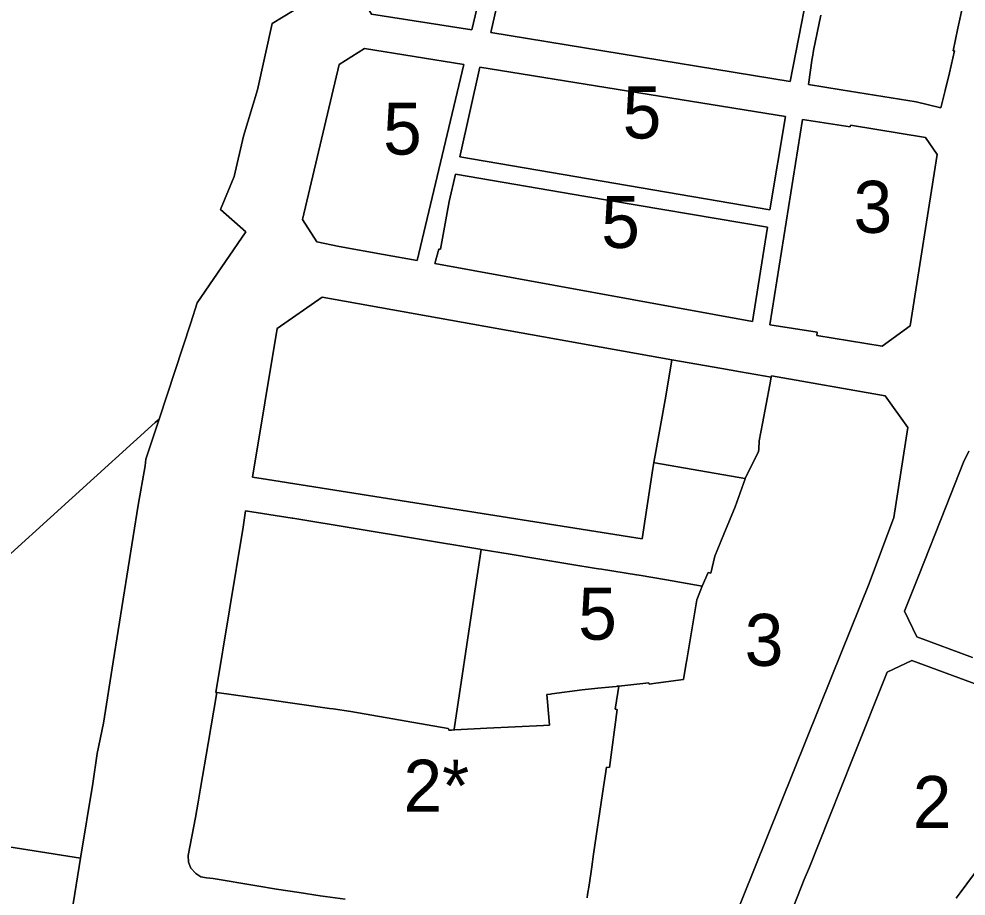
# Model space of a CAD drawing. Extents: x 598968 to 613553, y 4409678 to 4430833.
# Drawn here: x 607149.2 to 607367.7, y 4416375.4 to 4416577.8 of the extents above; entities that cross this region are included whole.
import ezdxf

# ---------------------------------------------------------------- set-up
doc = ezdxf.new("R2010")
doc.units = 0
for name, color, linetype in [('1', 7, 'Continuous'), ('Sòl Rústic Protegit', 7, 'Continuous'), ('ZONA 2. CARRERS DE CASES. Cases de trast', 7, 'Continuous'), ("ZONA 2_. CARRERS DE CASES. Afectades a ús d'aparcament", 7, 'Continuous'), ("ZONA 3. ILLES  D'EDIFICIS ENTRE MITGERES. EIXAMPLE.", 7, 'Continuous'), ('ZONA 5. CASES UNIFAMILIARS EN RENGLE', 7, 'Continuous')]:
    doc.layers.add(name, color=color, linetype=linetype)

msp = doc.modelspace()

# ---------------------------------------------------------------- linework, layer by layer
at = {"layer": '1'}
for points in [[(607253.6812, 4416575.2516), (607230.5315, 4416578.8312), (607227.1615, 4416584.5111), (607240.1011, 4416639.1907), (607245.621, 4416643.0107), (607268.9208, 4416639.2012)], [(607258.0512, 4416574.6517), (607264.851, 4416604.5115), (607302.0556, 4416598.43), (607333.0202, 4416593.3728), (607329.7503, 4416576.7029), (607327.1804, 4416563.333)], [(607241.0715, 4416522.002), (607233.2926, 4416523.3829), (607223.1303, 4416525.2361), (607217.9218, 4416526.2916), (607214.6264, 4416531.5106), (607223.0816, 4416567.2612), (607228.9215, 4416570.9112), (607251.8312, 4416567.2717)], [(607322.5005, 4416533.7433), (607250.9113, 4416545.9319), (607255.5612, 4416566.5918), (607326.1005, 4416555.2335)], [(607354.8802, 4416506.9342), (607348.3603, 4416502.2341), (607333.3105, 4416504.7138), (607333.4205, 4416505.4638), (607322.5006, 4416507.1636), (607330.0304, 4416554.5732), (607341.0102, 4416552.8834), (607341.0702, 4416553.2434), (607358.38, 4416550.4337), (607361.05, 4416546.4438)], [(607245.1615, 4416521.3521), (607246.0815, 4416524.6721), (607246.4815, 4416524.6321), (607248.4704, 4416535.6503), (607249.9414, 4416541.9019), (607280.021, 4416536.7625), (607321.9505, 4416529.7133), (607318.4807, 4416507.9235)], [(607299.8135, 4416499.0644), (607219.1718, 4416513.5817), (607208.792, 4416506.2916), (607203.0922, 4416472.0218), (607206.5921, 4416471.4919), (607293.0312, 4416457.7836), (607295.4811, 4416474.0434), (607295.7181, 4416475.3748), (607298.4534, 4416490.7421)], [(607322.7915, 4416495.1106), (607322.7639, 4416495.1107), (607315.7097, 4416496.3465), (607311.3629, 4416497.1079), (607299.8241, 4416499.1291), (607299.8135, 4416499.0644), (607298.4534, 4416490.7421), (607295.7181, 4416475.3748), (607295.9347, 4416475.3316), (607316.7188, 4416471.7323), (607316.7987, 4416471.7185), (607316.8655, 4416471.8538), (607319.8252, 4416477.9597), (607319.9193, 4416478.5087), (607320.0407, 4416480.4138), (607320.8007, 4416484.4437), (607322.4545, 4416493.3044)], [(607163.4465, 4416384.1234), (607166.2737, 4416401.3843), (607167.2644, 4416408.2936), (607168.6943, 4416415.2534), (607170.9668, 4416429.4365), (607176.7537, 4416465.5525), (607178.3436, 4416474.6524), (607178.5036, 4416476.1423), (607181.5374, 4416485.3831), (607180.6417, 4416484.6408), (607142.2689, 4416449.8628), (607128.5101, 4416464.9802), (607049.7261, 4416480.7842), (607041.8879, 4416473.8212), (607034.4301, 4416467.1962), (607020.2629, 4416454.6108), (607008.6601, 4416449.6102), (606998.8249, 4416429.3186), (606991.3041, 4416413.8024), (606990.5165, 4416412.1774), (607085.9131, 4416396.7506), (607115.4633, 4416391.7362), (607117.6201, 4416391.3702)], [(607255.8616, 4416455.3329), (607255.5325, 4416455.3874), (607212.3821, 4416462.5321), (607212.2621, 4416462.5521), (607201.5169, 4416464.241), (607200.9222, 4416460.5219), (607194.6724, 4416422.3422), (607194.8418, 4416422.3183), (607194.8424, 4416422.3222), (607205.8323, 4416420.8025), (607206.4601, 4416420.7127), (607220.864, 4416418.6531), (607221.6723, 4416418.5376), (607225.7621, 4416417.9528), (607248.2585, 4416414.0139), (607248.2618, 4416414.0133), (607248.2908, 4416413.9366), (607248.4018, 4416413.6433), (607249.0068, 4416413.6737), (607249.6118, 4416413.7041), (607249.6418, 4416413.9037), (607254.1827, 4416444.1494)]]:
    msp.add_lwpolyline(points, close=True, dxfattribs=at)
for points in [[(607212.6721, 4416579.7513), (607207.6022, 4416576.7012), (607204.2785, 4416561.4214), (607201.0126, 4416550.7016), (607198.9026, 4416541.3817), (607195.7021, 4416533.7618), (607201.5675, 4416528.6372), (607190.3531, 4416512.222), (607188.8352, 4416507.6121), (607181.5374, 4416485.3831), (607178.5036, 4416476.1423), (607178.3436, 4416474.6524), (607176.7537, 4416465.5525), (607170.9668, 4416429.4365), (607168.6943, 4416415.2534), (607167.2644, 4416408.2936), (607166.2737, 4416401.3843), (607163.4465, 4416384.1234), (607161.4063, 4416371.6676)], [(607366.9798, 4416580.8535), (607365.8299, 4416575.6036), (607364.7899, 4416570.4336), (607365.0599, 4416570.3836), (607363.9099, 4416565.3236), (607362.8965, 4416561.2696), (607361.9498, 4416557.2437), (607356.22, 4416558.6336), (607338.9002, 4416561.3633), (607331.4103, 4416562.6331), (607332.2003, 4416568.6831), (607332.2803, 4416568.9031), (607332.5403, 4416570.443), (607334.2002, 4416578.663)], [(607224.4559, 4416374.6879), (607218.7376, 4416375.4571), (607213.8916, 4416376.2053), (607208.6375, 4416377.004), (607204.084, 4416377.7469), (607194.0554, 4416379.3943), (607192.51, 4416379.6008), (607191.1526, 4416379.8327), (607190.0126, 4416380.5926), (607188.8726, 4416381.8326), (607188.2926, 4416383.2226), (607188.2391, 4416384.7221), (607189.9626, 4416393.4725), (607190.5526, 4416397.0225), (607191.1125, 4416400.2424), (607192.8725, 4416410.5923), (607194.8418, 4416422.3183), (607194.6724, 4416422.3422), (607200.9222, 4416460.5219), (607201.5169, 4416464.241), (607212.2621, 4416462.5521), (607212.3821, 4416462.5321), (607255.5325, 4416455.3874), (607255.8616, 4416455.3329), (607255.8665, 4416455.3357), (607262.5552, 4416454.2279), (607268.4785, 4416453.2604), (607276.7563, 4416451.8876), (607282.3888, 4416450.9775), (607282.913, 4416450.897), (607283.6455, 4416450.7844), (607291.6767, 4416449.5076), (607292.3377, 4416449.3946), (607298.5834, 4416448.3268), (607306.8637, 4416446.8654), (607306.8772, 4416446.8978), (607308.211, 4416450.0639), (607308.861, 4416449.8839), (607309.7609, 4416453.8039), (607311.8709, 4416458.8639), (607313.1559, 4416462.0139), (607314.4409, 4416465.1638), (607316.7508, 4416471.6238), (607316.7987, 4416471.7185), (607316.7188, 4416471.7323), (607295.9347, 4416475.3316), (607295.7181, 4416475.3748), (607295.4811, 4416474.0434), (607293.0312, 4416457.7836), (607206.5921, 4416471.4919), (607203.0922, 4416472.0218), (607208.792, 4416506.2916), (607219.1718, 4416513.5817), (607299.8135, 4416499.0644), (607299.8241, 4416499.1291), (607311.3629, 4416497.1079), (607315.7097, 4416496.3465), (607322.7639, 4416495.1107), (607322.7915, 4416495.1106), (607322.8406, 4416495.3736), (607349.0704, 4416490.7641), (607354.3303, 4416483.4643), (607351.0404, 4416462.6845), (607345.3706, 4416447.5046), (607336.7307, 4416426.0747), (607313.1112, 4416367.1749)], [(607369.2138, 4416430.4319), (607356.3705, 4416435.2149), (607353.5672, 4416441.0944), (607356.7654, 4416449.1648), (607363.1304, 4416465.315), (607363.1446, 4416465.3509), (607367.1502, 4416475.5146), (607368.3879, 4416478.0158)], [(607368.3879, 4416478.0158), (607367.1502, 4416475.5146), (607363.1446, 4416465.3509), (607363.1304, 4416465.315), (607356.7654, 4416449.1648), (607353.5672, 4416441.0944), (607356.3705, 4416435.2149), (607369.2138, 4416430.4319)], [(607325.5011, 4416366.6452), (607330.411, 4416379.1751), (607331.631, 4416382.0451), (607336.2109, 4416393.685), (607341.62, 4416407.2132), (607349.5406, 4416427.0349), (607355.2105, 4416429.725), (607385.6902, 4416418.5156), (607382.1903, 4416409.3257), (607379.5603, 4416411.3356), (607374.7104, 4416405.2856), (607374.9704, 4416405.1856), (607373.2804, 4416403.1556), (607381.3603, 4416396.6858), (607377.5854, 4416391.5608), (607377.7055, 4416391.711), (607379.9804, 4416389.5359), (607387.2703, 4416382.4361), (607385.9204, 4416372.4362)]]:
    msp.add_lwpolyline(points, dxfattribs=at)
at = {"layer": 'Sòl Rústic Protegit'}
for points in [[(607142.2689, 4416449.8628), (607180.6417, 4416484.6408), (607181.5374, 4416485.3831), (607188.8352, 4416507.6121), (607190.3531, 4416512.222), (607201.5675, 4416528.6372), (607195.7021, 4416533.7618), (607198.9026, 4416541.3817), (607201.0126, 4416550.7016), (607204.2785, 4416561.4214), (607207.6022, 4416576.7012), (607212.6721, 4416579.7513)], [(607161.4063, 4416371.6676), (607163.4465, 4416384.1234), (607117.6201, 4416391.3702)]]:
    msp.add_lwpolyline(points, dxfattribs=at)
at = {"layer": 'ZONA 2. CARRERS DE CASES. Cases de trast'}
for points in [[(607334.2002, 4416578.663), (607332.5403, 4416570.443), (607332.2803, 4416568.9031), (607332.2003, 4416568.6831), (607331.4103, 4416562.6331), (607338.9002, 4416561.3633), (607356.22, 4416558.6336), (607361.9498, 4416557.2437), (607362.8965, 4416561.2696), (607363.9099, 4416565.3236), (607365.0599, 4416570.3836), (607364.7899, 4416570.4336), (607365.8299, 4416575.6036), (607366.9798, 4416580.8535)], [(607365.4306, 4416374.8958), (607366.3606, 4416376.1358), (607374.0904, 4416386.4658), (607375.4404, 4416388.2658), (607375.4549, 4416388.2879), (607377.322, 4416391.1277), (607377.7055, 4416391.711), (607377.5854, 4416391.5608), (607381.3603, 4416396.6858), (607373.2804, 4416403.1556), (607374.9704, 4416405.1856), (607374.7104, 4416405.2856), (607379.5603, 4416411.3356), (607382.1903, 4416409.3257), (607385.6902, 4416418.5156), (607355.2105, 4416429.725), (607349.5406, 4416427.0349), (607341.62, 4416407.2132), (607336.2109, 4416393.685), (607331.631, 4416382.0451), (607330.411, 4416379.1751), (607325.5011, 4416366.6452)], [(607385.9204, 4416372.4362), (607387.2703, 4416382.4361), (607379.9804, 4416389.5359), (607377.7055, 4416391.711), (607377.322, 4416391.1277), (607375.4549, 4416388.2879), (607375.4404, 4416388.2658), (607374.0904, 4416386.4658), (607366.3606, 4416376.1358), (607365.4306, 4416374.8958)]]:
    msp.add_lwpolyline(points, dxfattribs=at)
at = {"layer": "ZONA 2_. CARRERS DE CASES. Afectades a ús d'aparcament"}
msp.add_lwpolyline([(607280.3177, 4416374.9462), (607280.4172, 4416375.7313), (607280.7477, 4416377.8843), (607281.3762, 4416382.1063), (607281.7893, 4416385.0136), (607283.8515, 4416399.0041), (607284.7515, 4416405.134), (607285.5014, 4416405.014), (607287.2614, 4416418.4039), (607286.7714, 4416418.4639), (607287.3949, 4416422.35), (607287.6169, 4416423.81), (607287.2328, 4416423.7832), (607287.029, 4416423.7626), (607286.9858, 4416423.7585), (607282.7485, 4416423.342), (607279.1255, 4416422.9603), (607272.1445, 4416422.033), (607271.8332, 4416421.986), (607270.9916, 4416421.8736), (607271.1533, 4416420.2), (607271.6616, 4416414.8237), (607271.6096, 4416414.8211), (607270.2616, 4416414.7536), (607257.1317, 4416414.0834), (607249.7773, 4416413.7125), (607249.6118, 4416413.7041), (607249.0068, 4416413.6737), (607248.4018, 4416413.6433), (607248.2908, 4416413.9366), (607248.2618, 4416414.0133), (607248.2585, 4416414.0139), (607225.7621, 4416417.9528), (607221.6723, 4416418.5376), (607220.864, 4416418.6531), (607206.4601, 4416420.7127), (607205.8323, 4416420.8025), (607194.8424, 4416422.3222), (607194.8418, 4416422.3183), (607192.8725, 4416410.5923), (607191.1125, 4416400.2424), (607190.5526, 4416397.0225), (607189.9626, 4416393.4725), (607188.2391, 4416384.7221), (607188.2926, 4416383.2226), (607188.8726, 4416381.8326), (607190.0126, 4416380.5926), (607191.1526, 4416379.8327), (607192.51, 4416379.6008), (607194.0554, 4416379.3943), (607204.084, 4416377.7469), (607208.6375, 4416377.004), (607213.8916, 4416376.2053), (607218.7376, 4416375.4571), (607224.4559, 4416374.6879)], dxfattribs=at)
at = {"layer": "ZONA 3. ILLES  D'EDIFICIS ENTRE MITGERES. EIXAMPLE."}
msp.add_lwpolyline([(607330.0304, 4416554.5732), (607322.5006, 4416507.1636), (607333.4205, 4416505.4638), (607333.3105, 4416504.7138), (607348.3603, 4416502.2341), (607354.8802, 4416506.9342), (607361.05, 4416546.4438), (607358.38, 4416550.4337), (607341.0702, 4416553.2434), (607341.0102, 4416552.8834)], close=True, dxfattribs=at)
msp.add_lwpolyline([(607313.1112, 4416367.1749), (607336.7307, 4416426.0747), (607345.3706, 4416447.5046), (607351.0404, 4416462.6845), (607354.3303, 4416483.4643), (607349.0704, 4416490.7641), (607322.8406, 4416495.3736), (607322.7915, 4416495.1106), (607322.4545, 4416493.3044), (607320.8007, 4416484.4437), (607320.0407, 4416480.4138), (607319.9193, 4416478.5087), (607319.8252, 4416477.9597), (607316.8655, 4416471.8538), (607316.7987, 4416471.7185), (607316.7508, 4416471.6238), (607314.4409, 4416465.1638), (607313.1559, 4416462.0139), (607311.8709, 4416458.8639), (607309.7609, 4416453.8039), (607308.861, 4416449.8839), (607308.211, 4416450.0639), (607306.8772, 4416446.8978), (607306.8637, 4416446.8654), (607306.8743, 4416446.8635), (607305.6001, 4416443.7508), (607303.2958, 4416429.8479), (607303.0957, 4416428.6686), (607302.5335, 4416425.3545), (607296.1269, 4416424.4838), (607294.6003, 4416424.2763), (607294.5983, 4416424.2814), (607294.546, 4416424.6015), (607294.539, 4416424.6007), (607294.5197, 4416424.5985), (607287.6427, 4416423.8128), (607287.6294, 4416423.8114), (607287.6169, 4416423.81), (607287.3949, 4416422.35), (607286.7714, 4416418.4639), (607287.2614, 4416418.4039), (607285.5014, 4416405.014), (607284.7515, 4416405.134), (607283.8515, 4416399.0041), (607281.7893, 4416385.0136), (607281.3762, 4416382.1063), (607280.7477, 4416377.8843), (607280.4172, 4416375.7313), (607280.3177, 4416374.9462)], dxfattribs=at)
at = {"layer": 'ZONA 5. CASES UNIFAMILIARS EN RENGLE'}
for points in [[(607268.9208, 4416639.2012), (607245.621, 4416643.0107), (607240.1011, 4416639.1907), (607227.1615, 4416584.5111), (607230.5315, 4416578.8312), (607253.6812, 4416575.2516)], [(607329.7503, 4416576.7029), (607333.0202, 4416593.3728), (607302.0556, 4416598.43), (607264.851, 4416604.5115), (607258.0512, 4416574.6517), (607327.1804, 4416563.333)], [(607251.8312, 4416567.2717), (607228.9215, 4416570.9112), (607223.0816, 4416567.2612), (607214.6264, 4416531.5106), (607217.9218, 4416526.2916), (607223.1303, 4416525.2361), (607233.2926, 4416523.3829), (607241.0715, 4416522.002)], [(607326.1005, 4416555.2335), (607255.5612, 4416566.5918), (607250.9113, 4416545.9319), (607322.5005, 4416533.7433)], [(607321.9505, 4416529.7133), (607280.021, 4416536.7625), (607249.9414, 4416541.9019), (607248.4704, 4416535.6503), (607246.4815, 4416524.6321), (607246.0815, 4416524.6721), (607245.1615, 4416521.3521), (607318.4807, 4416507.9235)], [(607306.8637, 4416446.8654), (607298.5834, 4416448.3268), (607292.3377, 4416449.3946), (607291.6767, 4416449.5076), (607283.6455, 4416450.7844), (607282.913, 4416450.897), (607282.3888, 4416450.9775), (607276.7563, 4416451.8876), (607268.4785, 4416453.2604), (607262.5552, 4416454.2279), (607255.8665, 4416455.3357), (607255.8616, 4416455.3329), (607254.1827, 4416444.1494), (607249.6418, 4416413.9037), (607249.6118, 4416413.7041), (607249.7773, 4416413.7125), (607257.1317, 4416414.0834), (607270.2616, 4416414.7536), (607271.6096, 4416414.8211), (607271.6616, 4416414.8237), (607271.1533, 4416420.2), (607270.9916, 4416421.8736), (607271.8332, 4416421.986), (607272.1445, 4416422.033), (607279.1255, 4416422.9603), (607282.7485, 4416423.342), (607286.9858, 4416423.7585), (607287.029, 4416423.7626), (607287.2328, 4416423.7832), (607287.6169, 4416423.81), (607287.6294, 4416423.8114), (607287.6427, 4416423.8128), (607294.5197, 4416424.5985), (607294.539, 4416424.6007), (607294.546, 4416424.6015), (607294.5983, 4416424.2814), (607294.6003, 4416424.2763), (607296.1269, 4416424.4838), (607302.5335, 4416425.3545), (607303.0957, 4416428.6686), (607303.2958, 4416429.8479), (607305.6001, 4416443.7508), (607306.8743, 4416446.8635)]]:
    msp.add_lwpolyline(points, close=True, dxfattribs=at)

# ---------------------------------------------------------------- texts
at = {"layer": 'ZONA 2. CARRERS DE CASES. Cases de trast'}
msp.add_text('2', height=12, dxfattribs=at).set_placement((607355.4407, 4416391.0705))
at = {"layer": "ZONA 2_. CARRERS DE CASES. Afectades a ús d'aparcament"}
msp.add_text('2*', height=12, dxfattribs=at).set_placement((607237.928, 4416394.8271))
at = {"layer": "ZONA 3. ILLES  D'EDIFICIS ENTRE MITGERES. EIXAMPLE."}
for p in [(607341.7753, 4416528.4036), (607316.6617, 4416428.4842)]:
    msp.add_text('3', height=12, dxfattribs=at).set_placement(p)
at = {"layer": 'ZONA 5. CASES UNIFAMILIARS EN RENGLE'}
for p in [(607288.5059, 4416550.1676), (607233.2288, 4416546.4566), (607283.556, 4416524.9127), (607278.2431, 4416434.5199)]:
    msp.add_text('5', height=12, dxfattribs=at).set_placement(p)

doc.saveas('drawing.dxf')
